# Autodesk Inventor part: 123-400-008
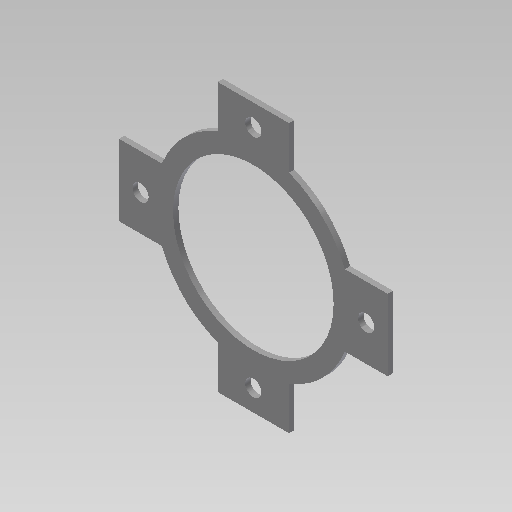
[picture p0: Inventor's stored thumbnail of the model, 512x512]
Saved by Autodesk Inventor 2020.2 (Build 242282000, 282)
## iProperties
Created: 2006-08
Part Number: 123-400-008
Document SubType Name: Modeling
Designer: F.Stasiak
Description: Dystans
Material: Stal
Mass: 18589.9 g
Surface Area: 3856.02 cm^2
Volume: 2368.14 cm^3
Density: 7.85 g/cm^3
Appearance: Stal
Manager: www.cadconsulting.pl
Company: Fabian Stasiak CAD Consulting
KODMAT: 14-1358
Author: F.Stasiak
Subject: Zbiór ćwiczeń. Autodesk Inventor 2020. Kurs podstawowy
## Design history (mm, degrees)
sketch "Szkic1"
  geometry: L1 (100, 256.174)-(100, 376.174) reference; L2 (100, 376.174)-(-100, 376.174) reference; L3 (-100, 376.174)-(-100, 256.174) reference; L4 (-256.174, 100)-(-376.174, 100) reference; L5 (-376.174, 100)-(-376.174, -100) reference; L6 (-376.174, -100)-(-256.174, -100) reference; L7 (-100, -256.174)-(-100, -376.174) reference; L8 (-100, -376.174)-(100, -376.174) reference; L9 (100, -376.174)-(100, -256.174) reference; L10 (256.174, -100)-(376.174, -100) reference; L11 (376.174, -100)-(376.174, 100) reference; L12 (376.174, 100)-(256.174, 100) reference; C1 r 22.835 at (-316.174, 0) reference; C2 r 22.835 at (0, -316.174) reference; C3 r 22.835 at (316.174, 0) reference; C4 r 22.835 at (0, 316.174) reference; C5 r 225 at (0, 0) reference; A1 r 275 centre (0, 0) between (256.174, 100) and (100, 256.174) reference; A2 r 275 centre (0, 0) between (-100, 256.174) and (-256.174, 100) reference; A3 r 275 centre (0, 0) between (-256.174, -100) and (-100, -256.174) reference; A4 r 275 centre (0, 0) between (100, -256.174) and (256.174, -100) reference
extrude "Wyciągnięcie proste1" new body sketch "Szkic1" distance "d0" = 15; taper "d1" = 0 deg
node "Bryła1"
node "Korpusy bryłowe"
node "Korpusy powierzchniowe"
node "Odniesienie1"
